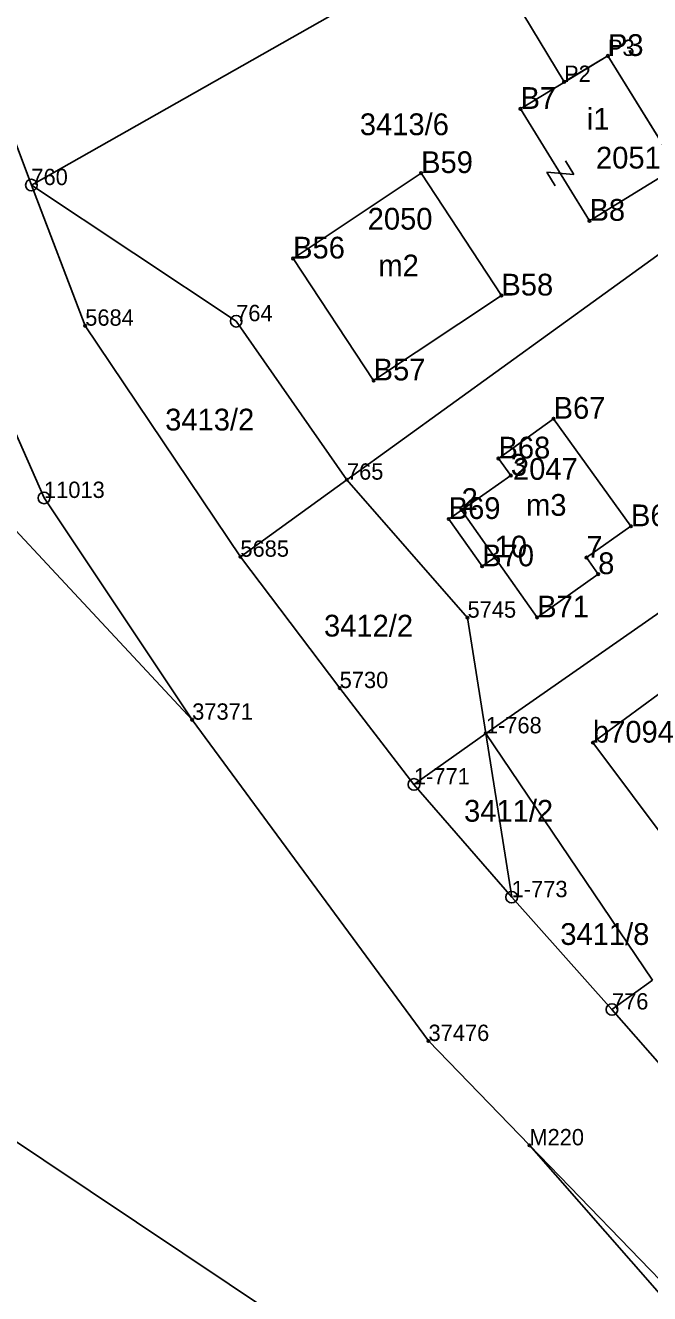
# Model space of a CAD drawing. Extents: x 7492083 to 7492670, y 5466693 to 5467065.
# Drawn here: x 7492163.8 to 7492206.8, y 5466933.4 to 5467020.8 of the extents above; entities that cross this region are included whole.
import ezdxf

# ---------------------------------------------------------------- set-up
doc = ezdxf.new("R2010")
doc.units = 0
for name, color, linetype in [('202-punkt graniczny', 7, 'Continuous'), ('202-punkt graniczny-Atr103', 7, 'Continuous'), ('203-punkt graniczny', 7, 'Continuous'), ('203-punkt graniczny-Atr103', 7, 'Continuous'), ('211-numer działki ewidencyjnej', 7, 'Continuous'), ('217-kontur klasyfikacyjny', 7, 'Continuous'), ('218-kontur użytku gruntowego', 7, 'Continuous'), ('219-działka ewidencyjna', 7, 'Continuous'), ('312-budynek ewidencyjny', 7, 'Continuous'), ('312-oznaczenie budynku ewidencyjnego', 7, 'Continuous'), ('312-oznaczenie budynku ewidencyjnego-Atr117', 7, 'Continuous'), ('320-blok - kondygnacja nadziemna', 7, 'Continuous'), ('991-Przehaczenie', 7, 'Continuous'), ('Punkt budynku', 7, 'Continuous'), ('Punkt budynku-Atr103', 7, 'Continuous'), ('Punkt budynku-Atr104', 7, 'Continuous')]:
    doc.layers.add(name, color=color, linetype=linetype)

# ---------------------------------------------------------------- blocks, each defined once
blk = doc.blocks.new('202')
blk.add_circle((0, 0), 0.4)
blk = doc.blocks.new('203')
blk.add_circle((0, 0), 0.09)
blk = doc.blocks.new('PUNKTBUD')
blk.add_circle((0, 0), 0.09)
blk = doc.blocks.new('991')
for p, q in [((-0.55, 0.75), (0.55, 0.75)), ((0.55, 0.75), (-0.55, -0.75)), ((-0.55, -0.75), (0.55, -0.75))]:
    blk.add_line(p, q)

msp = doc.modelspace()

# ---------------------------------------------------------------- linework, layer by layer
at = {"layer": '217-kontur klasyfikacyjny'}
for points in [[(7492164.2, 5467009.8), (7492192.7, 5467025.97)], [(7492159.74, 5467021.69), (7492164.2, 5467009.8)]]:
    msp.add_lwpolyline(points, dxfattribs=at)
at = {"layer": '218-kontur użytku gruntowego'}
for points in [[(7492164.2, 5467009.8), (7492192.7, 5467025.97)], [(7492159.74, 5467021.69), (7492164.2, 5467009.8)], [(7492164.2, 5467009.8), (7492178.31, 5467000.42)], [(7492178.31, 5467000.42), (7492185.94, 5466989.5)], [(7492175.28, 5466972.96), (7492153.1, 5466996.74)], [(7492185.94, 5466989.5), (7492194.25, 5466979.99)], [(7492194.25, 5466979.99), (7492195.51, 5466972.02)], [(7492191.56, 5466950.82), (7492175.28, 5466972.96)], [(7492195.51, 5466972.02), (7492206.99, 5466955)], [(7492203.36, 5466916.98), (7492145.88, 5466955.43)], [(7492198.51, 5466943.63), (7492191.56, 5466950.82)], [(7492219.52, 5466919.65), (7492198.51, 5466943.63)]]:
    msp.add_lwpolyline(points, dxfattribs=at)
at = {"layer": '219-działka ewidencyjna'}
for points in [[(7492151.34, 5467044.08), (7492164.2, 5467009.8)], [(7492194.76, 5467027.11), (7492200.9, 5467016.91)], [(7492164.2, 5467009.8), (7492192.7, 5467025.97)], [(7492200.9, 5467016.91), (7492203.92, 5467018.7)], [(7492203.92, 5467018.7), (7492210.85, 5467007.5)], [(7492153.07, 5467015.46), (7492165.07, 5466988.24)], [(7492164.2, 5467009.8), (7492167.91, 5467000.11)], [(7492164.2, 5467009.8), (7492178.31, 5467000.42)], [(7492185.94, 5466989.5), (7492210.85, 5467007.5)], [(7492167.91, 5467000.11), (7492178.6, 5466984.19)], [(7492178.31, 5467000.42), (7492185.94, 5466989.5)], [(7492153.1, 5466996.74), (7492175.28, 5466972.96)], [(7492178.6, 5466984.19), (7492185.94, 5466989.5)], [(7492185.94, 5466989.5), (7492194.25, 5466979.99)], [(7492165.07, 5466988.24), (7492175.28, 5466972.96)], [(7492178.6, 5466984.19), (7492185.44, 5466975.14)], [(7492195.51, 5466972.02), (7492211.75, 5466983.33)], [(7492194.25, 5466979.99), (7492195.51, 5466972.02)], [(7492185.44, 5466975.14), (7492190.56, 5466968.5)], [(7492175.28, 5466972.96), (7492191.56, 5466950.82)], [(7492190.56, 5466968.5), (7492195.51, 5466972.02)], [(7492195.51, 5466972.02), (7492197.29, 5466960.73)], [(7492195.51, 5466972.02), (7492206.99, 5466955)], [(7492190.56, 5466968.5), (7492197.29, 5466960.73)], [(7492197.29, 5466960.73), (7492204.2, 5466952.99)], [(7492145.88, 5466955.43), (7492203.36, 5466916.98)], [(7492204.2, 5466952.99), (7492206.99, 5466955)], [(7492204.2, 5466952.99), (7492220.55, 5466934.37)], [(7492191.56, 5466950.82), (7492198.51, 5466943.63)], [(7492198.51, 5466943.63), (7492260.93, 5466879.15)], [(7492198.51, 5466943.63), (7492219.52, 5466919.65)]]:
    msp.add_lwpolyline(points, dxfattribs=at)
at = {"layer": '312-budynek ewidencyjny'}
for points in [[(7492197.9, 5467015.05), (7492203.92, 5467018.7)], [(7492203.92, 5467018.7), (7492208.66, 5467011.04)], [(7492202.65, 5467007.34), (7492197.9, 5467015.05)], [(7492208.66, 5467011.04), (7492202.65, 5467007.34)], [(7492182.23, 5467004.74), (7492191.05, 5467010.63)], [(7492191.05, 5467010.63), (7492196.58, 5467002.19)], [(7492187.78, 5466996.34), (7492182.23, 5467004.74)], [(7492196.58, 5467002.19), (7492187.78, 5466996.34)], [(7492196.38, 5466990.96), (7492200.18, 5466993.7)], [(7492200.18, 5466993.7), (7492205.51, 5466986.29)], [(7492197.23, 5466989.78), (7492196.38, 5466990.96)], [(7492193.84, 5466987.41), (7492197.23, 5466989.78)], [(7492192.95, 5466986.79), (7492193.84, 5466987.41)], [(7492195.26, 5466983.53), (7492192.95, 5466986.79)], [(7492205.51, 5466986.29), (7492202.44, 5466984.13)], [(7492196.12, 5466984.14), (7492195.26, 5466983.53)], [(7492199.05, 5466980.01), (7492196.12, 5466984.14)], [(7492202.44, 5466984.13), (7492203.25, 5466982.99)], [(7492203.25, 5466982.99), (7492199.05, 5466980.01)], [(7492202.89, 5466971.38), (7492209.64, 5466976.35)], [(7492208.34, 5466964.08), (7492202.89, 5466971.38)]]:
    msp.add_lwpolyline(points, dxfattribs=at)
at = {"layer": '320-blok - kondygnacja nadziemna'}
for points in [[(7492193.84, 5466987.41), (7492197.23, 5466989.78), (7492196.38, 5466990.96), (7492200.18, 5466993.7), (7492205.51, 5466986.29), (7492202.44, 5466984.13), (7492203.25, 5466982.99), (7492199.05, 5466980.01), (7492196.12, 5466984.14)], [(7492192.95, 5466986.79), (7492193.84, 5466987.41), (7492196.12, 5466984.14), (7492195.26, 5466983.53)]]:
    msp.add_lwpolyline(points, close=True, dxfattribs=at)

# ---------------------------------------------------------------- block references
at = {"layer": '202-punkt graniczny'}
for p in [(7492164.2, 5467009.8), (7492178.31, 5467000.42), (7492165.07, 5466988.24), (7492190.56, 5466968.5), (7492197.29, 5466960.73), (7492204.2, 5466952.99)]:
    msp.add_blockref('202', p, dxfattribs=at)
at = {"layer": '203-punkt graniczny'}
for p in [(7492203.92, 5467018.7), (7492200.9, 5467016.91), (7492167.91, 5467000.11), (7492185.94, 5466989.5), (7492178.6, 5466984.19), (7492194.25, 5466979.99), (7492185.44, 5466975.14), (7492175.28, 5466972.96), (7492195.51, 5466972.02), (7492191.56, 5466950.82), (7492198.51, 5466943.63)]:
    msp.add_blockref('203', p, dxfattribs=at)
at = {"layer": '991-Przehaczenie', "rotation": -58.36100000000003}
msp.add_blockref('991', (7492200.64, 5467010.61), dxfattribs=at)
at = {"layer": 'Punkt budynku'}
for p in [(7492203.92, 5467018.7), (7492197.9, 5467015.05), (7492191.05, 5467010.63), (7492202.65, 5467007.34), (7492182.23, 5467004.74), (7492196.58, 5467002.19), (7492187.78, 5466996.34), (7492200.18, 5466993.7), (7492196.38, 5466990.96), (7492197.23, 5466989.78), (7492193.84, 5466987.41), (7492192.95, 5466986.79), (7492205.51, 5466986.29), (7492196.12, 5466984.14), (7492202.44, 5466984.13), (7492195.26, 5466983.53), (7492203.25, 5466982.99), (7492199.05, 5466980.01), (7492202.89, 5466971.38)]:
    msp.add_blockref('PUNKTBUD', p, dxfattribs=at)

# ---------------------------------------------------------------- texts
at = {"layer": '202-punkt graniczny-Atr103'}
for s, p in [('760', (7492164.2, 5467009.8)), ('764', (7492178.31, 5467000.42)), ('11013', (7492165.07, 5466988.24)), ('1-771', (7492190.56, 5466968.5)), ('1-773', (7492197.29, 5466960.73)), ('776', (7492204.2, 5466952.99))]:
    msp.add_text(s, height=1.125, dxfattribs=at).set_placement(p)
at = {"layer": '203-punkt graniczny-Atr103'}
for s, p in [('P3', (7492203.92, 5467018.7)), ('P2', (7492200.9, 5467016.91)), ('5684', (7492167.91, 5467000.11)), ('765', (7492185.94, 5466989.5)), ('5685', (7492178.6, 5466984.19)), ('5745', (7492194.25, 5466979.99)), ('5730', (7492185.44, 5466975.14)), ('37371', (7492175.28, 5466972.96)), ('1-768', (7492195.51, 5466972.02)), ('37476', (7492191.56, 5466950.82)), ('M220', (7492198.51, 5466943.63))]:
    msp.add_text(s, height=1.125, dxfattribs=at).set_placement(p)
at = {"layer": '211-numer działki ewidencyjnej'}
for s, p in [('3413/6', (7492186.83, 5467013.24)), ('3413/2', (7492173.42, 5466992.89)), ('3412/2', (7492184.36, 5466978.69)), ('3411/2', (7492194.01, 5466965.93)), ('3411/8', (7492200.64, 5466957.44))]:
    msp.add_text(s, height=1.5, dxfattribs=at).set_placement(p)
at = {"layer": '312-oznaczenie budynku ewidencyjnego'}
for s, p in [('2051', (7492203.1, 5467010.94)), ('2050', (7492187.37, 5467006.73)), ('2047', (7492197.38, 5466989.49))]:
    msp.add_text(s, height=1.5, dxfattribs=at).set_placement(p)
at = {"layer": '312-oznaczenie budynku ewidencyjnego-Atr117'}
for s, p in [('i1', (7492202.47, 5467013.61)), ('m2', (7492188.106, 5467003.51)), ('m3', (7492198.28, 5466987.01))]:
    msp.add_text(s, height=1.5, dxfattribs=at).set_placement(p)
at = {"layer": 'Punkt budynku-Atr103'}
for s, p in [('P3', (7492203.92, 5467018.7)), ('B7', (7492197.9, 5467015.05)), ('B59', (7492191.05, 5467010.63)), ('B8', (7492202.65, 5467007.34)), ('B56', (7492182.23, 5467004.74)), ('B58', (7492196.58, 5467002.19)), ('B57', (7492187.78, 5466996.34)), ('B67', (7492200.18, 5466993.7)), ('B68', (7492196.38, 5466990.96)), ('B69', (7492192.95, 5466986.79)), ('B66', (7492205.51, 5466986.29)), ('B70', (7492195.26, 5466983.53)), ('B71', (7492199.05, 5466980.01)), ('b7094', (7492202.89, 5466971.38))]:
    msp.add_text(s, height=1.5, dxfattribs=at).set_placement(p)
at = {"layer": 'Punkt budynku-Atr104'}
for s, p in [('3', (7492197.23, 5466989.78)), ('2', (7492193.84, 5466987.41)), ('10', (7492196.12, 5466984.14)), ('7', (7492202.44, 5466984.13)), ('8', (7492203.25, 5466982.99))]:
    msp.add_text(s, height=1.5, dxfattribs=at).set_placement(p)

doc.saveas('drawing.dxf')
